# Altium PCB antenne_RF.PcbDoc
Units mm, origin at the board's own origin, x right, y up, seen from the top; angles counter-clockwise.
Board outline 10.6 x 60 mm, 2 copper layers (Top Layer, Bottom Layer), stack 0.836 mm thick; 0 components, 0 nets, 0 pads, 0 vias.
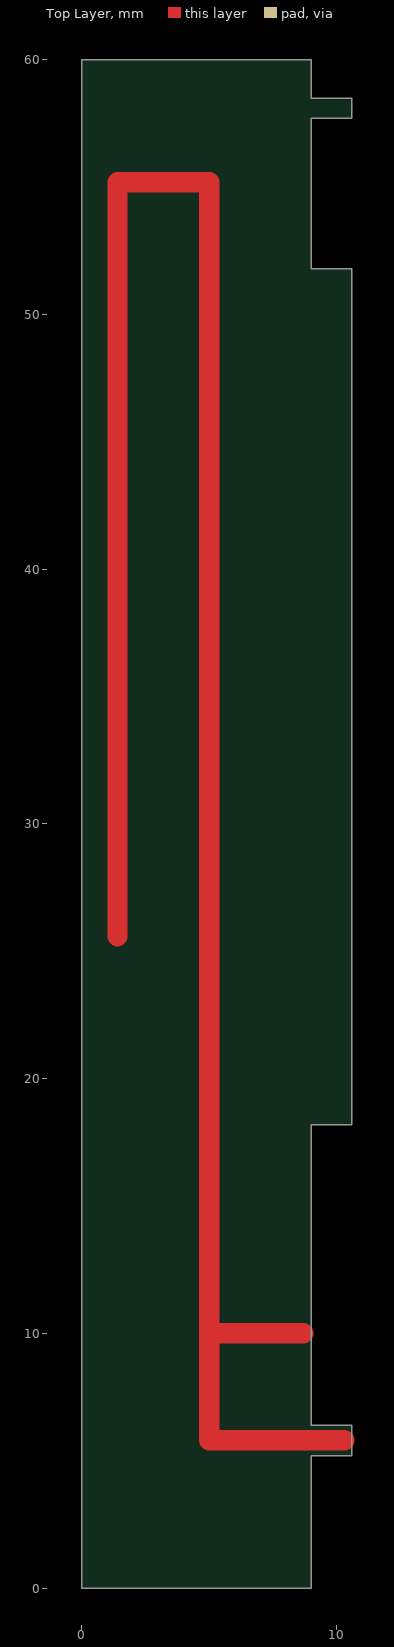
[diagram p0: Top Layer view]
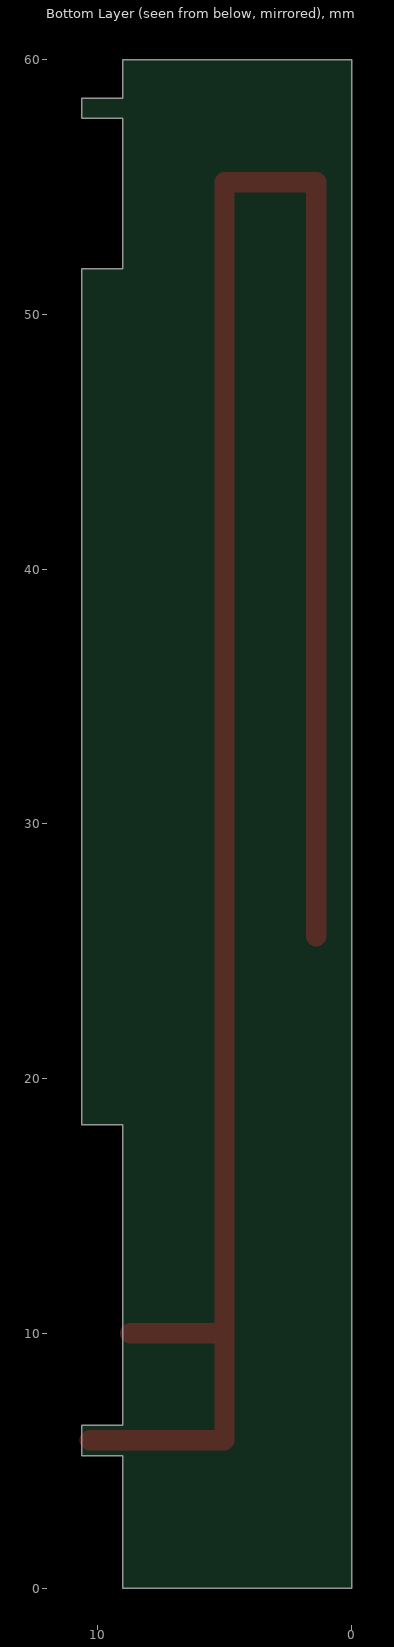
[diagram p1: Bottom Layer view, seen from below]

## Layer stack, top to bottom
Top Solder: solder mask 0.0102, Solder Resist, Dk 3.5
Top Layer: signal copper 0.018
Dielectric 1: dielectric 0.8, FR-4, Dk 4.8
Bottom Layer: signal copper 0.018
Bottom Solder: solder mask 0.0102, Solder Resist, Dk 3.5

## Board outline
10.6,58.5 9,58.5 9,60 0,60 0,0 9,0 9,5.2 10.6,5.2 10.6,6.4 9,6.4 9,18.2 10.6,18.2 10.6,51.8 9,51.8 9,57.7 10.6,57.7

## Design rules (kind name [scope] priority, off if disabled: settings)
Clearance [All] p1: gap=0.254 ignorepadtopadclearanceinfootprint=FALSE except(0: Arc-Hole Track-Hole SMDPad-Hole THPad-Hole Via-Hole Fill-Hole Poly-Hole Region-Hole Text-Hole)
PolygonConnect [All] p1: connectstyle=Relief reliefconductorwidth=0.254 reliefentries=4 polygonreliefangle="90 Angle" airgapwidth=0.254
RoutingVias [All] p1: holewidth=0.711 width=1.27 viastyle="Through Hole" minholewidth=0.711 minwidth=1.27 maxholewidth=0.711 maxwidth=1.27
SolderMaskExpansion [All] p1: expansion=0.102
Width [All] p1: maxlimit=1 minlimit=0.254 preferedwidth=0.8
30 further rules are at their usual default settings.

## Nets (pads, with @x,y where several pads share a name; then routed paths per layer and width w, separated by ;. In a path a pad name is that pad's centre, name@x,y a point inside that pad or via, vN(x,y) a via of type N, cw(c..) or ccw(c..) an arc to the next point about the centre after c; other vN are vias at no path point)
copper on no net: | length 91.5
  Top Layer w0.8: 1.4,25.6 1.4,55.1 ; 1.4,55.2 5,55.2 5,5.8 10.3,5.8 ; 5,10 8.7,10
